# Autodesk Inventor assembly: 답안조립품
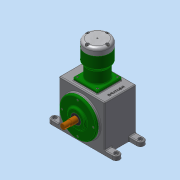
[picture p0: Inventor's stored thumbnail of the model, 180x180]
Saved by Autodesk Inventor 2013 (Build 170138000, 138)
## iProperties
Created: 2016-11
Part Number: 답안조립품
Document SubType Name: Assembly
Designer: Administrator
Author: Administrator
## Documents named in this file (16)
- C:\Users\Administrator\Desktop\361108v1008\답안조립품.iam
- C:\Users\Administrator\Desktop\361108v1008\본체.ipt
- C:\Users\Administrator\Desktop\361108v1008\메인크랭크축.ipt
- C:\Users\Administrator\Desktop\361108v1008\크랭크보조축.ipt
- C:\Users\Administrator\Desktop\361108v1008\베어링 20 x 47 x 14.ipt
- C:\Users\Administrator\Desktop\361108v1008\앞커버.ipt
- C:\Users\Administrator\Desktop\361108v1008\베어링 NA 4902.ipt
- C:\Users\Administrator\Desktop\361108v1008\오일 실 20 35 8.ipt
- C:\Users\Administrator\Desktop\361108v1008\볼트 M4 x 8.ipt
- C:\Users\Administrator\Desktop\361108v1008\커넥팅로드.ipt
- C:\Users\Administrator\Desktop\361108v1008\피스톤.ipt
- C:\Users\Administrator\Desktop\361108v1008\피스톤핀.ipt
- C:\Users\Administrator\Desktop\361108v1008\실린더.ipt
- C:\Users\Administrator\Desktop\361108v1008\실린더헤드.ipt
- C:\Users\Administrator\Desktop\361108v1008\가변스프링.ipt
- C:\Users\Administrator\Desktop\361108v1008\볼트 M5 x 20.ipt
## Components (15 placed, 5 different names)
1. 피스톤:1
2. 피스톤핀:1
3. 가변스프링:1
4. ISO 4762 M4 x 8:1
5. ISO 4762 M4 x 8:2
6. ISO 4762 M4 x 8:3
7. ISO 4762 M4 x 8:4
8. ISO 4762 M4 x 8:5
9. ISO 4762 M4 x 8:6
10. ISO 4762 M4 x 8:7
11. ISO 4762 M4 x 8:8
12. ISO 4762 M5 x 20:1
13. ISO 4762 M5 x 20:2
14. ISO 4762 M5 x 20:3
15. ISO 4762 M5 x 20:4
